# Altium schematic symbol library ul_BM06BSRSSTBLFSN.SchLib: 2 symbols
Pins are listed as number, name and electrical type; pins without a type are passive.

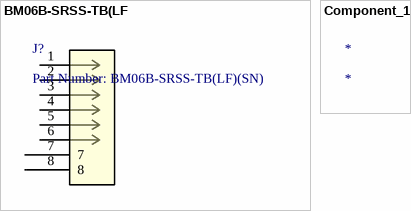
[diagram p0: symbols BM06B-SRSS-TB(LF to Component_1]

## BM06B-SRSS-TB(LF
designator J?, comment Part Number: BM06B-SRSS-TB(LF)(SN)
No Description Available; Built_By: EMA_Justin; Vendor: JST; SourceLibrary: JST_2020-02-24
footprint CONN_BM06B-SRSS-
pins: 1, 2, 3, 4, 5, 6, 7, 8

## Component_1
designator *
